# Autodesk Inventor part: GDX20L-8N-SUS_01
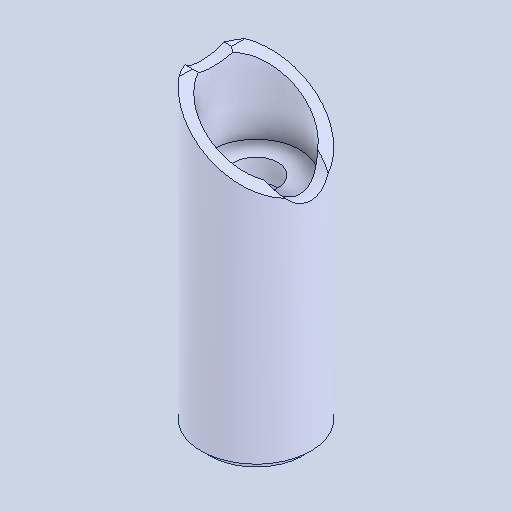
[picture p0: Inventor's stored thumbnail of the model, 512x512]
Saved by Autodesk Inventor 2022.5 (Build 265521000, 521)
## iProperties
Created: 2024-06
Part Number: GDX20L-8N-SUS_01
Material: 一般
Document SubType Name: Modeling
Designer: ImaoCorp
Density: 1 g/cm^3
Appearance: 既定
Author: ImaoCorp
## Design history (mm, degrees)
feature "GDX20L-8N-SUS_01"
node "ソリッド1"
